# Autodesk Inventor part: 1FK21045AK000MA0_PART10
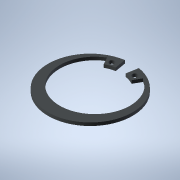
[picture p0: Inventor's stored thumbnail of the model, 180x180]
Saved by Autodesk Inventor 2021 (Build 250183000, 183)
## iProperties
Created: 2025-04
Part Number: 1FK21045AK000MA0_PART10
Material: Generic
Catalog Web Link: www.3dfindit.com
Description: -Servo synchronous motor
Document SubType Name: Modeling
Designer: psAdmin
Mass: 0.642463 g
Surface Area: 12.3927 cm^2
Volume: 0.642463 cm^3
Density: 1 g/cm^3
Appearance: PSOLRGB-212-217-219
Category: PARTsolutions
Title: 1FK21045AK000MA0_PART10
Author: Cadenas PARTsolutions
Comments: Servo synchronous motor
Sending System: PARTsolutions
Preprocessor: ST-DEVELOPER v19.3
PSOL_IDENT_0: {$CADENAS_DATA/23d-libs/siemens_ag/_cat_/3d/2f/1fk21045ak000ma0.prj},216 {VTYP=3D},{NB=1FK21045AK000
PSOL_IDENT_1: MA0_PART10},{LINA=1FK21045AK000MA0_PART10},{NN=1FK21045AK000MA0_PART10},{NOPRJ=TRUE},{DATE=19.08.202
PSOL_IDENT_2: 5 14:00:34},{GEOMDATE=30.07.2025 02:01:24},{VERSION=},{LINEID=10},{WBVAR=},{WBNUMERIC=}  {NB=1FK2104
PSOL_IDENT_3: 5AK000MA0_PART10},{LINA=1FK21045AK000MA0_PART10},{KT=DUMMY},{PREVIEW=../../../_pool_/a9/69/p_d211_xx
PSOL_IDENT_4: _00818j.png},{DESCSHORT=SIMOTICS S-1FK2 HD, SINAMICS S210 3AC 400V-480V, 1.7 Nm, 6000 rpm},{DESCLONG=
PSOL_IDENT_5: SIMOTICS S-1FK2 HD servo motor M0=2.4 Nm; PN = 1.07 kW at nN=6000 rpm (380-480 V); PN = 0.75 kW at n
PSOL_IDENT_6: N=3000 rpm (200-240 V); degree of protection IP64; cylindrical shaft D19x40mm; absolute encoder 22-b
PSOL_IDENT_7: it + 12-bit multiturn (encoder AM22DQC); with OCC interface; plug size M17, rotatable; SIMOTICS S-1F
PSOL_IDENT_8: K2 servomotorfor a wide range of uses in industrial environments. SIMOTICS S‑1FK2 servomotors are co
PSOL_IDENT_9: mpact synchronous motors with a high dynamic performance that set themselves apart as a result of th
PSOL_IDENT_10: eir high power density, degree of protection and overload capability. The motors are available in tw
PSOL_IDENT_11: o variants: as High Dynamic variant (highest dynamic performance as a result of the low intrinsic mo
PSOL_IDENT_12: ment of inertia for applications demanding a high dynamic performance with low moved masses) - and a
PSOL_IDENT_13: s Compact variant (precise and stable closed-loop control for medium up to large moved masses as a r
PSOL_IDENT_14: esult of a medium intrinsic moment of inertia). SIMOTICSS‑1FK2 servomotors fully exploit their stren
PSOL_IDENT_15: gths in a system with the SINAMICSS210 frequency converter and simple connection using the one cable
PSOL_IDENT_16: connection (OCC). Advantages include the short control and positioning times, fast and precise corr
PSOL_IDENT_17: ection of disturbing quantities as well as stable control with a high dynamic performance. The servo
PSOL_IDENT_18: motors can be configured to address a wide range of requirements. For example with and without hold
PSOL_IDENT_19: ing brake, IP64 or IP65 degree of protection, singleturn or multiturn absolute encoders - to name ju
PSOL_IDENT_20: st a few. Further, the servomotors are available in different shaft heights extending from 20 to 100
PSOL_IDENT_21: . A shaft sealing ring is available to achieve an IP65 degree of protection and for subsequent mount
PSOL_IDENT_22: ing at the motor or as spare part. SIMOTICS - the optimum motor for each and every motion control ap
PSOL_IDENT_23: plication.},{INTNO=804766789342},{SUPPLIERALTNO=1FK2104-5AK00-0MA0},{MANUID=1FK21045AK000MA0},{MANUN
PSOL_IDENT_24: AME=Siemens},{MANUTYPEDESC=Synchronous motor 1FK2-HD 2,39 Nm},{AAU732=SIMOTICS},{AAO057=S-1FK2},{AAU
PSOL_IDENT_25: 734=SIMOTICS S-1FK2 HD servo motor M0=2.4 Nm; PN = 1.07 kW at nN=6000 rpm (380-480 V); PN = 0.75 kW
PSOL_IDENT_26: at nN=3000 rpm (200-240 V); degree of protection IP64; cylindrical shaft D19x40mm; absolute encoder
PSOL_IDENT_27: 22-bit + 12-bit multiturn (encoder AM22DQC); with OCC interface; plug size M17, rotatable;},{AAW338=
PSOL_IDENT_28: Synchronous motor 1FK2-HD 2,39 Nm},{AAO742=SIMOTICS},{AAO663=4042948691151},{NOCUPEROU=1},{PRICEQUAN
PSOL_IDENT_29: TITY=1},{QUANTITYMIN=1},{QUANTITYINT=1},{CTN=85015100},{COO=DE},{AAO676=1FK2104-5AK00-0MA0},{AAO677=
PSOL_IDENT_30: Siemens AG},{ORDERUNIT=C62},{CONTENTUNIT=C62}
NB: 1FK21045AK000MA0_PART10
NT: Servo synchronous motor
NBSYN: $MANUID._PART10
LINA: 1FK21045AK000MA0_PART10
CATALOG: SIEMENS
PREVIEW: ../../../_pool_/a9/69/p_d211_xx_00818j.png
DESCSHORT: SIMOTICS S-1FK2 HD, SINAMICS S210 3AC 400V-480V, 1.7 Nm, 6000 rpm
DESCLONG: SIMOTICS S-1FK2 HD servo motor M0=2.4 Nm; PN = 1.07 kW at nN=6000 rpm (380-480 V); PN = 0.75 kW at nN=3000 rpm (200-240 V); degree of protection IP64; cylindric
INTNO: 804766789342
SUPPLIERALTNO: 1FK2104-5AK00-0MA0
MANUID: 1FK21045AK000MA0
MANUNAME: Siemens
MANUTYPEDESC: Synchronous motor 1FK2-HD 2,39 Nm
AAU732: SIMOTICS
AAO057: S-1FK2
AAU734: SIMOTICS S-1FK2 HD servo motor M0=2.4 Nm; PN = 1.07 kW at nN=6000 rpm (380-480 V); PN = 0.75 kW at nN=3000 rpm (200-240 V); degree of protection IP64; cylindric
AAW338: Synchronous motor 1FK2-HD 2,39 Nm
AAO742: SIMOTICS
AAO663: 4042948691151.0
NOCUPEROU: 1
PRICEQUANTITY: 1
QUANTITYMIN: 1
QUANTITYINT: 1
CTN: 85015100
COO: DE
ARTICLENO: 1FK21045AK000MA0_PART10
BOMINFO: 1FK21045AK000MA0_PART10
CREATOR: CADENAS GmbH
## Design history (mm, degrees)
feature "2025_04_17_15_39_51_0728"
body "Solid1"
